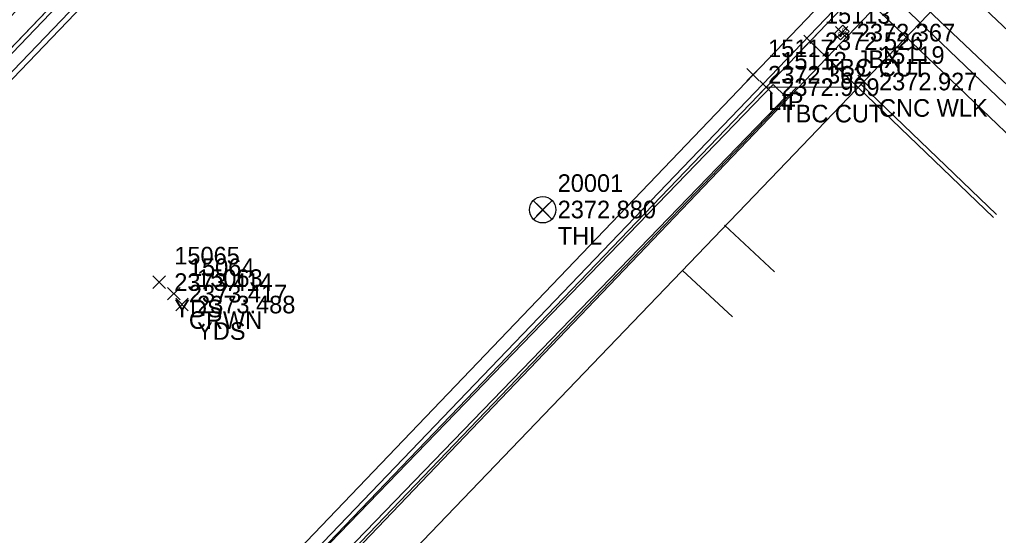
# Model space of a CAD drawing. Extents: x 2377639 to 2379738, y 729875 to 732734.
# Drawn here: x 2378181.6 to 2378292.6, y 730368 to 730426.6 of the extents above; entities that cross this region are included whole.
import ezdxf

# ---------------------------------------------------------------- set-up
doc = ezdxf.new("R2010")
doc.units = 0
for name, color, linetype in [('Default', 7, 'Continuous'), ('DES_ROADWAY_Sidewalk', 7, 'Continuous'), ('TOPO_CURBGTR_Back-of-Curb', 7, 'Continuous'), ('TOPO_CURBGTR_Face-of-Curb', 7, 'Continuous'), ('TOPO_CURBGTR_Lip-of-Gutter', 7, 'Continuous'), ('TOPO_DATA_Elevations', 7, 'Continuous'), ('TOPO_ELEC_Cable_Overhead-Exist', 7, 'Continuous'), ('TOPO_GEOLOGY_Test-Hole', 7, 'Continuous'), ('TOPO_LNDSCP_Misc', 7, 'Continuous'), ('TOPO_MISC_Flat-Asphalt', 7, 'Continuous'), ('TOPO_SAN_Plastic-Pipe', 7, 'Continuous'), ('TOPO_STORM_Line-Other', 7, 'Continuous'), ('TOPO_SW_Back', 7, 'Continuous'), ('TOPO_TELE_Overhead-Line', 7, 'Continuous'), ('TOPO_TRFSIGNL_Traf-Sig-Misc', 7, 'Continuous'), ('TOPO_TV_Cable-Overhead', 7, 'Continuous'), ('TOPO_WTRUTIL_Line', 7, 'Continuous')]:
    doc.layers.add(name, color=color, linetype=linetype)

# ---------------------------------------------------------------- blocks, each defined once
blk = doc.blocks.new('JCTBOX_5')
at = {"layer": 'Default'}
for p, q in [((-0.0086, 0.0064), (0.0086, 0.0064)), ((-0.0086, 0.0064), (-0.0086, -0.0064)), ((0.0086, 0.0064), (0.0086, -0.0064)), ((-0.0086, -0.0064), (0.0086, -0.0064))]:
    blk.add_line(p, q, dxfattribs=at)
blk.add_text('SIG', height=0.00635, dxfattribs=at).set_placement((-0.0063, -0.0031))
blk = doc.blocks.new('BORE_1')
at = {"layer": 'Default'}
for p, q in [((-0.135, 0.129), (0.135, -0.139)), ((0.137, 0.13), (-0.13, -0.142))]:
    blk.add_line(p, q, dxfattribs=at)
blk.add_circle((0.001, -0.003), 0.191, dxfattribs=at)

msp = doc.modelspace()

# ---------------------------------------------------------------- linework, layer by layer
at = {"layer": 'DES_ROADWAY_Sidewalk'}
for p, q in [((2378267.23, 730397.96), (2378261.57, 730403.23)), ((2378262.46, 730392.84), (2378256.8, 730398.11))]:
    msp.add_line(p, q, dxfattribs=at)
at = {"layer": 'TOPO_CURBGTR_Back-of-Curb'}
msp.add_line((2378292.09, 730404.11), (2378276.73, 730418.86), dxfattribs=at)
for points in [[(2378139.75, 730380.87), (2378148.64, 730390), (2378225.84, 730470.65), (2378251.52, 730497.43), (2378309.29, 730557.66), (2378317.46, 730566.28)], [(2378186.07, 730334.91), (2378191.86, 730341.37), (2378266.29, 730418.91), (2378294.6, 730448.49), (2378365.13, 730522.12)]]:
    msp.add_lwpolyline(points, dxfattribs=at)
at = {"layer": 'TOPO_CURBGTR_Face-of-Curb'}
msp.add_line((2378292.44, 730404.47), (2378277.08, 730419.22), dxfattribs=at)
for points in [[(2378140.26, 730380.67), (2378149, 730389.65), (2378226.2, 730470.3), (2378251.88, 730497.08), (2378309.66, 730557.31), (2378317.82, 730565.94)], [(2378185.7, 730335.25), (2378191.49, 730341.71), (2378265.93, 730419.26), (2378294.23, 730448.83), (2378364.76, 730522.46)]]:
    msp.add_lwpolyline(points, dxfattribs=at)
at = {"layer": 'TOPO_CURBGTR_Lip-of-Gutter'}
for points in [[(2378319.9, 730566.2), (2378310.75, 730556.45), (2378281.26, 730525.51), (2378150.03, 730388.75), (2378141.73, 730380.11)], [(2378184.52, 730336.46), (2378190.48, 730342.62), (2378264.81, 730420.32), (2378293.2, 730449.96), (2378361.38, 730521)]]:
    msp.add_lwpolyline(points, dxfattribs=at)
at = {"layer": 'TOPO_DATA_Elevations'}
for p, q in [((2378270.55, 730423.41), (2378271.96, 730424.83)), ((2378270.55, 730424.83), (2378271.96, 730423.41)), ((2378274.15, 730424.39), (2378275.57, 730425.8)), ((2378274.15, 730425.8), (2378275.57, 730424.39)), ((2378264.1, 730419.61), (2378265.51, 730421.03)), ((2378264.1, 730421.03), (2378265.51, 730419.61)), ((2378265.59, 730418.2), (2378267, 730419.62)), ((2378265.59, 730419.62), (2378267, 730418.2)), ((2378276.69, 730418.84), (2378278.1, 730420.26)), ((2378276.69, 730420.26), (2378278.1, 730418.84)), ((2378240.21, 730404.31), (2378241.63, 730405.72)), ((2378240.21, 730405.72), (2378241.63, 730404.31)), ((2378196.7, 730396.07), (2378198.12, 730397.49)), ((2378196.7, 730397.49), (2378198.12, 730396.07)), ((2378198.37, 730394.77), (2378199.78, 730396.18)), ((2378198.37, 730396.18), (2378199.78, 730394.77)), ((2378199.3, 730393.52), (2378200.71, 730394.94)), ((2378199.3, 730394.94), (2378200.71, 730393.52))]:
    msp.add_line(p, q, dxfattribs=at)
at = {"layer": 'TOPO_ELEC_Cable_Overhead-Exist'}
msp.add_line((2378388.98, 730322.09), (2378222.92, 730481.5), dxfattribs=at)
at = {"layer": 'TOPO_LNDSCP_Misc'}
msp.add_lwpolyline([(2378191.67, 730341.16), (2378267.07, 730419.2), (2378268.51, 730417.8), (2378193.11, 730339.77)], close=True, dxfattribs=at)
at = {"layer": 'TOPO_MISC_Flat-Asphalt'}
msp.add_lwpolyline([(2378142.93, 730387.65), (2378190.64, 730437.48), (2378192.44, 730435.75), (2378144.73, 730385.92)], close=True, dxfattribs=at)
at = {"layer": 'TOPO_SAN_Plastic-Pipe'}
msp.add_line((2378505.67, 730223.51), (2378230.32, 730485.7), dxfattribs=at)
at = {"layer": 'TOPO_STORM_Line-Other'}
for q in [(2378187, 730332.08), (2378188.38, 730333.53)]:
    msp.add_line((2378608.31, 730773.03), q, dxfattribs=at)
at = {"layer": 'TOPO_SW_Back'}
for p, q in [((2378193.65, 730339.54), (2378269.74, 730418.89)), ((2378199.09, 730338.02), (2378268.61, 730410.41))]:
    msp.add_line(p, q, dxfattribs=at)
for points in [[(2378397.25, 730507), (2378388.6, 730515.23), (2378372.58, 730519.09), (2378370.25, 730516.61), (2378296.45, 730439.47), (2378277.39, 730419.55), (2378268.61, 730410.41)], [(2378271.27, 730424.11), (2378276.73, 730418.86), (2378266.29, 730418.91)]]:
    msp.add_lwpolyline(points, dxfattribs=at)
at = {"layer": 'TOPO_TELE_Overhead-Line'}
msp.add_line((2378390.57, 730323.64), (2378224.56, 730483.12), dxfattribs=at)
at = {"layer": 'TOPO_TV_Cable-Overhead'}
msp.add_line((2378432.32, 730287.11), (2378021.81, 730677.94), dxfattribs=at)
at = {"layer": 'TOPO_WTRUTIL_Line'}
msp.add_line((2378133.36, 730370.41), (2378391.81, 730640.09), dxfattribs=at)

# ---------------------------------------------------------------- block references
at = {"layer": 'TOPO_GEOLOGY_Test-Hole', "xscale": 7.8740000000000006, "yscale": 7.8740000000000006}
msp.add_blockref('BORE_1', (2378240.92, 730405.02), dxfattribs=at)
at = {"layer": 'TOPO_TRFSIGNL_Traf-Sig-Misc', "xscale": 78.74000000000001, "yscale": 78.74000000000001, "rotation": 44.89219106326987}
msp.add_blockref('JCTBOX_5', (2378274.86, 730425.1), dxfattribs=at)

# ---------------------------------------------------------------- texts
at = {"layer": 'TOPO_DATA_Elevations'}
for s, p in [('15113', (2378272.96, 730426.12)), ('2372.367', (2378276.57, 730424.1)), ('2372.526', (2378272.96, 730423.12)), ('15117', (2378266.51, 730422.32)), ('15112', (2378268, 730420.91)), ('JBX', (2378276.57, 730421.1)), ('15119', (2378279.1, 730421.55)), ('TBC CUT', (2378272.96, 730420.12)), ('2372.362', (2378266.51, 730419.32)), ('2372.927', (2378279.1, 730418.55)), ('2372.909', (2378268, 730417.91)), ('LIP', (2378266.51, 730416.32)), ('CNC WLK', (2378279.1, 730415.55)), ('TBC CUT', (2378268, 730414.91)), ('20001', (2378242.63, 730407.02)), ('2372.880', (2378242.63, 730404.02)), ('THL', (2378242.63, 730401.02)), ('15065', (2378199.12, 730398.78)), ('15064', (2378200.78, 730397.47)), ('15063', (2378201.71, 730396.23)), ('2373.414', (2378199.12, 730395.78)), ('2373.417', (2378200.78, 730394.47)), ('YDS', (2378199.12, 730392.78)), ('2373.488', (2378201.71, 730393.23)), ('CRWN', (2378200.78, 730391.47)), ('YDS', (2378201.71, 730390.23))]:
    msp.add_text(s, height=2, dxfattribs=at).set_placement(p)

doc.saveas('drawing.dxf')
